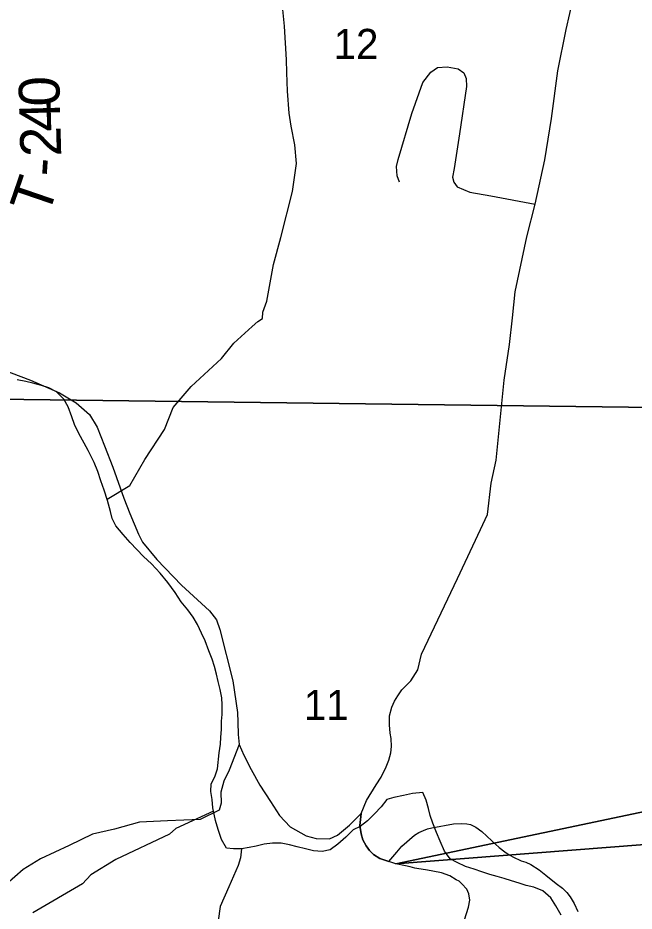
# Model space of a CAD drawing. Extents: x 0 to 34, y 0 to 22.
# Drawn here: x 4.552 to 5.41, y 17.402 to 18.646 of the extents above; entities that cross this region are included whole.
import ezdxf

# ---------------------------------------------------------------- set-up
doc = ezdxf.new("R2010")
doc.units = 0
for name, color, linetype in [('GM_X_County_Road', 7, 'Continuous'), ('GM_X_Minor_River', 7, 'Continuous'), ('GM_X_Section', 7, 'Continuous'), ('GM_X_Section_Text', 7, 'Continuous'), ('GM_X_State_Route', 7, 'Continuous'), ('GM_X_Township_Road', 7, 'Continuous'), ('GM_X_Township_Road_Text', 7, 'Continuous'), ('SC_Shading1', 7, 'Continuous'), ('SH_Data', 7, 'Continuous')]:
    doc.layers.add(name, color=color, linetype=linetype)

msp = doc.modelspace()

# ---------------------------------------------------------------- linework, layer by layer
at = {"layer": 'GM_X_County_Road'}
for p, q in [((4.5292, 18.1568), (4.5694, 18.1412)), ((4.5694, 18.1412), (4.6101, 18.1236)), ((4.6101, 18.1236), (4.6334, 18.11)), ((4.6334, 18.11), (4.6516, 18.0936)), ((4.6516, 18.0936), (4.6626, 18.0758)), ((4.6626, 18.0758), (4.6725, 18.0501)), ((4.6725, 18.0501), (4.684, 18.0203)), ((4.684, 18.0203), (4.6996, 17.9772)), ((4.6996, 17.9772), (4.7079, 17.9554)), ((4.7079, 17.9554), (4.7198, 17.9268)), ((4.7198, 17.9268), (4.7257, 17.9155)), ((4.7257, 17.9155), (4.7453, 17.8914)), ((4.7453, 17.8914), (4.78, 17.8558)), ((4.78, 17.8558), (4.8188, 17.8199)), ((4.8188, 17.8199), (4.8287, 17.8076)), ((4.8287, 17.8076), (4.833, 17.7942)), ((4.833, 17.7942), (4.8512, 17.7226)), ((4.8512, 17.7226), (4.8578, 17.6782)), ((4.8578, 17.6782), (4.8582, 17.665)), ((4.8582, 17.665), (4.8589, 17.6477)), ((4.8589, 17.6477), (4.8603, 17.634)), ((4.8603, 17.634), (4.8668, 17.619)), ((4.8668, 17.619), (4.8766, 17.599)), ((4.8766, 17.599), (4.8891, 17.577)), ((4.8891, 17.577), (4.9036, 17.5542)), ((4.9036, 17.5542), (4.9163, 17.535)), ((4.9163, 17.535), (4.9313, 17.5189)), ((5.0135, 17.5215), (5.0299, 17.5378)), ((5.0299, 17.5378), (5.0283, 17.5209)), ((4.9971, 17.5075), (5.0135, 17.5215)), ((5.1282, 17.5178), (5.1587, 17.5231)), ((5.1587, 17.5231), (5.1696, 17.5238)), ((5.1696, 17.5238), (5.177, 17.5233)), ((5.177, 17.5233), (5.182, 17.5223)), ((5.182, 17.5223), (5.1897, 17.5185)), ((4.9313, 17.5189), (4.9536, 17.5067)), ((5.0283, 17.5209), (5.0301, 17.5094)), ((5.0301, 17.5094), (5.0322, 17.5009)), ((5.1041, 17.5075), (5.1103, 17.5112)), ((5.1103, 17.5112), (5.1167, 17.5141)), ((5.1167, 17.5141), (5.1225, 17.5161)), ((5.1225, 17.5161), (5.1282, 17.5178)), ((5.1897, 17.5185), (5.1979, 17.5124)), ((5.1979, 17.5124), (5.2118, 17.4998)), ((4.9536, 17.5067), (4.9673, 17.503)), ((4.9673, 17.503), (4.9857, 17.5023)), ((4.9857, 17.5023), (4.9971, 17.5075)), ((5.0322, 17.5009), (5.0369, 17.4925)), ((5.0865, 17.4923), (5.1041, 17.5075)), ((5.2118, 17.4998), (5.2222, 17.4903)), ((5.0369, 17.4925), (5.0418, 17.4862)), ((5.0418, 17.4862), (5.0473, 17.4808)), ((5.0794, 17.4839), (5.0865, 17.4923)), ((5.2222, 17.4903), (5.2299, 17.4843)), ((5.2299, 17.4843), (5.2346, 17.4811)), ((5.0473, 17.4808), (5.0559, 17.4751)), ((5.0559, 17.4751), (5.0686, 17.4706)), ((5.0686, 17.4706), (5.0794, 17.4839)), ((5.2346, 17.4811), (5.2411, 17.4774)), ((5.2411, 17.4774), (5.2527, 17.4719)), ((5.2527, 17.4719), (5.2592, 17.4697)), ((5.2592, 17.4697), (5.2663, 17.4665)), ((5.2663, 17.4665), (5.2777, 17.4591)), ((5.2777, 17.4591), (5.2871, 17.4519)), ((5.2871, 17.4519), (5.3015, 17.4404)), ((5.3015, 17.4404), (5.3105, 17.4337)), ((5.3105, 17.4337), (5.3164, 17.4276)), ((5.3164, 17.4276), (5.3209, 17.4216)), ((5.3209, 17.4216), (5.3266, 17.4121)), ((5.3266, 17.4121), (5.3318, 17.4013))]:
    msp.add_line(p, q, dxfattribs=at)
at = {"layer": 'GM_X_Minor_River'}
for p, q in [((4.923, 18.6343), (4.921, 18.6578)), ((4.9261, 18.5876), (4.923, 18.6343)), ((4.9264, 18.5701), (4.9261, 18.5876)), ((4.9272, 18.5442), (4.9264, 18.5701)), ((4.9296, 18.5131), (4.9272, 18.5442)), ((4.9326, 18.4953), (4.9296, 18.5131)), ((4.9376, 18.4691), (4.9326, 18.4953)), ((4.9399, 18.4433), (4.9376, 18.4691)), ((4.9342, 18.4044), (4.9399, 18.4433)), ((4.9179, 18.3403), (4.9342, 18.4044)), ((4.908, 18.3024), (4.9179, 18.3403)), ((4.8987, 18.2513), (4.908, 18.3024)), ((4.8929, 18.236), (4.8987, 18.2513)), ((4.8927, 18.2273), (4.8929, 18.236)), ((4.8781, 18.216), (4.8859, 18.2233)), ((4.8859, 18.2233), (4.8927, 18.2273)), ((4.8528, 18.1927), (4.8781, 18.216)), ((4.8354, 18.1715), (4.8528, 18.1927)), ((4.7934, 18.1324), (4.8354, 18.1715)), ((4.563, 18.1394), (4.5511, 18.142)), ((4.5729, 18.1374), (4.563, 18.1394)), ((4.5848, 18.134), (4.5729, 18.1374)), ((4.5952, 18.1305), (4.5848, 18.134)), ((4.7682, 18.1031), (4.7934, 18.1324)), ((4.606, 18.1251), (4.5952, 18.1305)), ((4.6162, 18.1148), (4.606, 18.1251)), ((4.6222, 18.1043), (4.6162, 18.1148)), ((4.6272, 18.0904), (4.6222, 18.1043)), ((4.7562, 18.0725), (4.7682, 18.1031)), ((4.631, 18.0795), (4.6272, 18.0904)), ((4.6366, 18.0679), (4.631, 18.0795)), ((4.7286, 18.0309), (4.7562, 18.0725)), ((4.65, 18.0432), (4.6366, 18.0679)), ((4.6581, 18.0267), (4.65, 18.0432)), ((4.6634, 18.0139), (4.6581, 18.0267)), ((4.7081, 17.9944), (4.7286, 18.0309)), ((4.6676, 18.0011), (4.6634, 18.0139)), ((4.6722, 17.9879), (4.6676, 18.0011)), ((4.6762, 17.9756), (4.7081, 17.9944)), ((4.6768, 17.9736), (4.6722, 17.9879)), ((4.6811, 17.9585), (4.6768, 17.9736)), ((4.6833, 17.9487), (4.6811, 17.9585)), ((4.6882, 17.9386), (4.6833, 17.9487)), ((4.6984, 17.9263), (4.6882, 17.9386)), ((4.7083, 17.9152), (4.6984, 17.9263)), ((4.7177, 17.9056), (4.7083, 17.9152)), ((4.7271, 17.8956), (4.7177, 17.9056)), ((4.7381, 17.8857), (4.7271, 17.8956)), ((4.7499, 17.8724), (4.7381, 17.8857)), ((4.7606, 17.8594), (4.7499, 17.8724)), ((4.7709, 17.8456), (4.7606, 17.8594)), ((4.7793, 17.8326), (4.7709, 17.8456)), ((4.7887, 17.8215), (4.7793, 17.8326)), ((4.7959, 17.8114), (4.7887, 17.8215)), ((4.8023, 17.8009), (4.7959, 17.8114)), ((4.8076, 17.7889), (4.8023, 17.8009)), ((4.8129, 17.7784), (4.8076, 17.7889)), ((4.8179, 17.7641), (4.8129, 17.7784)), ((4.8224, 17.7525), (4.8179, 17.7641)), ((4.8258, 17.7423), (4.8224, 17.7525)), ((4.8284, 17.7317), (4.8258, 17.7423)), ((4.831, 17.7215), (4.8284, 17.7317)), ((4.8336, 17.7106), (4.831, 17.7215)), ((4.8359, 17.6988), (4.8336, 17.7106)), ((4.8365, 17.689), (4.8359, 17.6988)), ((4.8366, 17.6756), (4.8365, 17.689)), ((4.8357, 17.6661), (4.8366, 17.6756)), ((4.8353, 17.6547), (4.8357, 17.6661)), ((4.8345, 17.644), (4.8353, 17.6547)), ((4.8325, 17.6222), (4.834, 17.6341)), ((4.834, 17.6341), (4.8345, 17.644)), ((4.8298, 17.6), (4.8325, 17.6222)), ((4.8263, 17.5889), (4.8298, 17.6)), ((4.8213, 17.5788), (4.8263, 17.5889)), ((4.8205, 17.5685), (4.8213, 17.5788)), ((4.8223, 17.5572), (4.8205, 17.5685)), ((5.0755, 17.5598), (5.0657, 17.5572)), ((5.0891, 17.5629), (5.0755, 17.5598)), ((5.1015, 17.5656), (5.0891, 17.5629)), ((5.116, 17.5668), (5.1015, 17.5656)), ((5.1205, 17.5563), (5.116, 17.5668)), ((4.8235, 17.5454), (4.8223, 17.5572)), ((5.0576, 17.547), (5.0484, 17.5372)), ((5.0657, 17.5572), (5.0576, 17.547)), ((5.1239, 17.5446), (5.1205, 17.5563)), ((4.8244, 17.5409), (4.7719, 17.5168)), ((4.827, 17.528), (4.8235, 17.5454)), ((5.0484, 17.5372), (5.0388, 17.5274)), ((5.1261, 17.5347), (5.1239, 17.5446)), ((5.1298, 17.5242), (5.1261, 17.5347)), ((4.8308, 17.5156), (4.827, 17.528)), ((5.0388, 17.5274), (5.0284, 17.5195)), ((5.1348, 17.511), (5.1298, 17.5242)), ((4.7719, 17.5168), (4.7629, 17.5087)), ((4.8355, 17.5016), (4.8308, 17.5156)), ((5.0187, 17.515), (5.0084, 17.5048)), ((5.0284, 17.5195), (5.0187, 17.515)), ((5.1401, 17.499), (5.1348, 17.511)), ((4.7629, 17.5087), (4.6883, 17.4736)), ((4.8423, 17.4893), (4.8355, 17.5016)), ((5.0084, 17.5048), (4.9976, 17.4949)), ((5.1462, 17.4851), (5.1401, 17.499)), ((4.8522, 17.4884), (4.8423, 17.4893)), ((4.8632, 17.4884), (4.8522, 17.4884)), ((4.8633, 17.4884), (4.8622, 17.4757)), ((4.8742, 17.4903), (4.8632, 17.4884)), ((4.884, 17.4921), (4.8742, 17.4903)), ((4.895, 17.4951), (4.884, 17.4921)), ((4.9063, 17.4962), (4.895, 17.4951)), ((4.9185, 17.4962), (4.9063, 17.4962)), ((4.9304, 17.4939), (4.9185, 17.4962)), ((4.9407, 17.4912), (4.9304, 17.4939)), ((4.9526, 17.4885), (4.9407, 17.4912)), ((4.9637, 17.4855), (4.9526, 17.4885)), ((4.9755, 17.4847), (4.9637, 17.4855)), ((4.9868, 17.4873), (4.9755, 17.4847)), ((4.9976, 17.4949), (4.9868, 17.4873)), ((5.1538, 17.4747), (5.1462, 17.4851)), ((4.6883, 17.4736), (4.6535, 17.4524)), ((4.8622, 17.4757), (4.8589, 17.4654)), ((5.1634, 17.4693), (5.1538, 17.4747)), ((4.8589, 17.4654), (4.8458, 17.4355)), ((5.1754, 17.4639), (5.1634, 17.4693)), ((5.1873, 17.4601), (5.1754, 17.4639)), ((5.198, 17.4563), (5.1873, 17.4601)), ((4.6535, 17.4524), (4.642, 17.4397)), ((5.2092, 17.4528), (5.198, 17.4563)), ((5.2195, 17.4501), (5.2092, 17.4528)), ((5.2291, 17.447), (5.2195, 17.4501)), ((5.2391, 17.4438), (5.2291, 17.447)), ((4.642, 17.4397), (4.5728, 17.3993)), ((4.8458, 17.4355), (4.8338, 17.4082)), ((5.2498, 17.4408), (5.2391, 17.4438)), ((5.2598, 17.4376), (5.2498, 17.4408)), ((5.2702, 17.4349), (5.2598, 17.4376)), ((5.2829, 17.43), (5.2702, 17.4349)), ((5.2942, 17.4201), (5.2829, 17.43)), ((5.301, 17.4092), (5.2942, 17.4201)), ((4.8338, 17.4082), (4.8308, 17.388)), ((5.3082, 17.3961), (5.301, 17.4092))]:
    msp.add_line(p, q, dxfattribs=at)
at = {"layer": 'GM_X_Section'}
for p, q in [((5.5198, 18.1024), (4.5166, 18.1148)), ((4.5166, 18.1148), (5.5198, 18.1024))]:
    msp.add_line(p, q, dxfattribs=at)
at = {"layer": 'GM_X_State_Route'}
for p, q in [((5.3153, 18.63), (5.3262, 18.6778)), ((5.304, 18.5723), (5.3153, 18.63)), ((5.295, 18.506), (5.304, 18.5723)), ((5.2855, 18.4482), (5.295, 18.506)), ((5.2723, 18.3867), (5.2855, 18.4482)), ((5.2605, 18.341), (5.2723, 18.3867)), ((5.2444, 18.2642), (5.2605, 18.341)), ((5.2405, 18.2281), (5.2444, 18.2642)), ((5.2364, 18.1911), (5.2405, 18.2281)), ((5.2291, 18.1413), (5.2364, 18.1911)), ((5.2181, 18.0301), (5.2291, 18.1413)), ((5.2108, 17.9979), (5.2181, 18.0301)), ((5.2057, 17.9541), (5.2108, 17.9979)), ((5.1962, 17.9332), (5.2057, 17.9541)), ((5.1643, 17.8652), (5.1962, 17.9332)), ((5.114, 17.7597), (5.1643, 17.8652)), ((5.1088, 17.7379), (5.114, 17.7597)), ((5.0989, 17.7224), (5.1088, 17.7379)), ((5.0867, 17.7098), (5.0989, 17.7224)), ((5.0839, 17.7058), (5.0867, 17.7098)), ((5.0766, 17.6941), (5.081, 17.7018)), ((5.081, 17.7018), (5.0839, 17.7058)), ((5.0695, 17.6737), (5.0728, 17.686)), ((5.0728, 17.686), (5.0766, 17.6941)), ((5.0695, 17.6611), (5.0695, 17.6737)), ((5.0705, 17.6494), (5.0695, 17.6611)), ((5.0719, 17.6422), (5.0705, 17.6494)), ((5.0722, 17.6308), (5.0719, 17.6422)), ((5.0685, 17.6121), (5.0713, 17.6223)), ((5.0713, 17.6223), (5.0722, 17.6308)), ((5.0649, 17.6028), (5.0685, 17.6121)), ((5.0577, 17.5884), (5.0649, 17.6028)), ((5.0507, 17.5778), (5.0577, 17.5884)), ((5.0373, 17.556), (5.0507, 17.5778)), ((5.0299, 17.5378), (5.0373, 17.556)), ((5.0283, 17.5209), (5.0299, 17.5378)), ((5.0301, 17.5094), (5.0283, 17.5209)), ((5.0322, 17.5009), (5.0301, 17.5094)), ((5.0369, 17.4925), (5.0322, 17.5009)), ((5.0418, 17.4862), (5.0369, 17.4925)), ((5.0473, 17.4808), (5.0418, 17.4862)), ((5.0559, 17.4751), (5.0473, 17.4808)), ((5.0686, 17.4706), (5.0559, 17.4751)), ((5.0783, 17.4676), (5.0686, 17.4706)), ((5.0918, 17.4648), (5.0783, 17.4676)), ((5.0983, 17.4634), (5.0918, 17.4648)), ((5.1047, 17.4616), (5.0983, 17.4634)), ((5.1076, 17.4611), (5.1047, 17.4616)), ((5.1222, 17.4586), (5.1076, 17.4611)), ((5.1296, 17.4574), (5.1222, 17.4586)), ((5.1418, 17.4552), (5.1296, 17.4574)), ((5.1535, 17.4507), (5.1418, 17.4552)), ((5.1624, 17.4455), (5.1535, 17.4507)), ((5.1662, 17.4432), (5.1624, 17.4455)), ((5.1702, 17.4396), (5.1662, 17.4432)), ((5.1769, 17.4324), (5.1702, 17.4396)), ((5.1799, 17.4258), (5.1769, 17.4324)), ((5.1812, 17.4169), (5.1799, 17.4258)), ((5.1794, 17.407), (5.1812, 17.4169)), ((5.1737, 17.3895), (5.1794, 17.407))]:
    msp.add_line(p, q, dxfattribs=at)
at = {"layer": 'GM_X_Township_Road'}
for p, q in [((5.1159, 18.5561), (5.127, 18.5706)), ((5.127, 18.5706), (5.1361, 18.5771)), ((5.1361, 18.5771), (5.1498, 18.5777)), ((5.1498, 18.5777), (5.1648, 18.5751)), ((5.1648, 18.5751), (5.1727, 18.5693)), ((5.1727, 18.5693), (5.176, 18.5614)), ((5.1005, 18.513), (5.1159, 18.5561)), ((5.176, 18.5614), (5.1764, 18.5506)), ((5.1764, 18.5506), (5.1669, 18.4846)), ((5.0813, 18.4489), (5.1005, 18.513)), ((5.1669, 18.4846), (5.1594, 18.4364)), ((5.079, 18.4391), (5.0813, 18.4489)), ((5.0801, 18.4258), (5.079, 18.4391)), ((5.1594, 18.4364), (5.1573, 18.4243)), ((5.0832, 18.4173), (5.0801, 18.4258)), ((5.1573, 18.4243), (5.1589, 18.417)), ((5.1589, 18.417), (5.1634, 18.4106)), ((5.1634, 18.4106), (5.1812, 18.4035)), ((5.1812, 18.4035), (5.2104, 18.3982)), ((5.2104, 18.3982), (5.2723, 18.3867)), ((4.8603, 17.634), (4.8464, 17.598)), ((4.8464, 17.598), (4.8387, 17.5827)), ((4.8387, 17.5827), (4.8348, 17.5674)), ((4.8348, 17.5674), (4.8351, 17.5522)), ((4.8351, 17.5522), (4.8323, 17.5423)), ((4.8323, 17.5423), (4.8056, 17.5293)), ((4.7213, 17.5255), (4.6867, 17.5158)), ((4.7603, 17.5273), (4.7213, 17.5255)), ((4.8056, 17.5293), (4.7603, 17.5273)), ((4.6867, 17.5158), (4.6558, 17.5088)), ((4.6558, 17.5088), (4.6236, 17.493)), ((4.6236, 17.493), (4.5834, 17.4744)), ((4.5834, 17.4744), (4.5595, 17.4596)), ((4.5595, 17.4596), (4.536, 17.4394))]:
    msp.add_line(p, q, dxfattribs=at)
at = {"layer": 'SC_Shading1'}
msp.add_lwpolyline([(10.224, 18.5508), (10.224, 17.8673), (5.0783, 17.4676)], close=True, dxfattribs=at)
at = {"layer": 'SH_Data'}
for points in [[(10.224, 18.5508), (5.0783, 17.4676), (10.224, 17.8673)], [(5.1737, 17.3895), (5.1794, 17.407), (5.1794, 17.407), (5.1812, 17.4169), (5.1799, 17.4258), (5.1769, 17.4324), (5.1702, 17.4396), (5.1662, 17.4432), (5.1624, 17.4455), (5.1535, 17.4507), (5.1418, 17.4552), (5.1296, 17.4574), (5.1222, 17.4586), (5.1076, 17.4611), (5.1047, 17.4616), (5.0983, 17.4634), (5.0918, 17.4648), (5.0783, 17.4676)]]:
    msp.add_lwpolyline(points, dxfattribs=at)

# ---------------------------------------------------------------- texts
at = {"layer": 'GM_X_Section_Text'}
for s, p in [('12', (4.9917, 18.5889)), ('11', (4.9501, 17.6681))]:
    msp.add_text(s, height=0.04186, rotation=0, dxfattribs=at).set_placement(p)
at = {"layer": 'GM_X_Township_Road_Text'}
for s, rotation, p in [('0', 91.0721, (4.6105, 18.5232)), ('4', 91.6364, (4.6115, 18.4883)), ('2', 91.5723, (4.6125, 18.4533)), ('-', 86.1417, (4.6108, 18.4241)), ('T', 71.0839, (4.5938, 18.368))]:
    msp.add_text(s, height=0.0568, rotation=rotation, dxfattribs=at).set_placement(p)

doc.saveas('drawing.dxf')
